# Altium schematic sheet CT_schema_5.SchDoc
size 298 x 247 mm
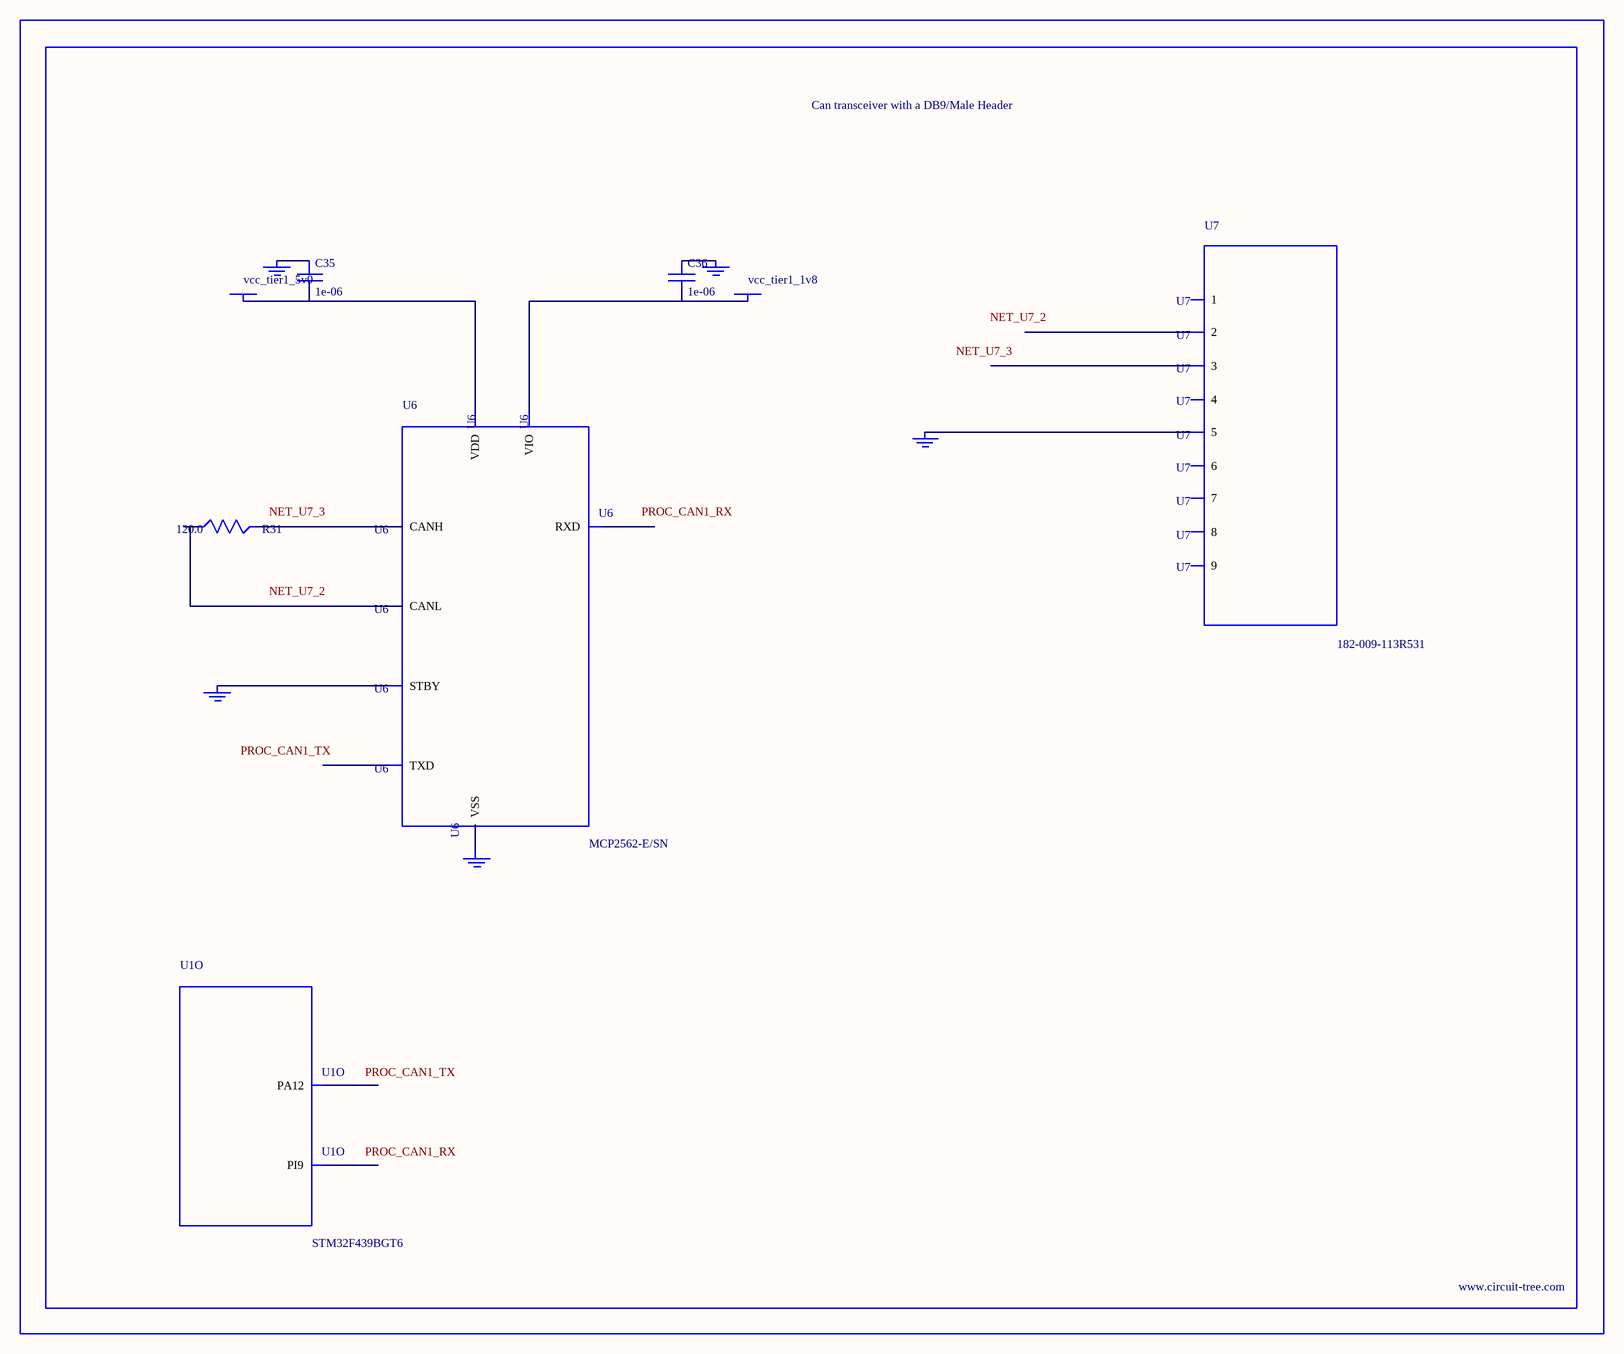
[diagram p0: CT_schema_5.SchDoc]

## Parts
BORDER4  (no value)
C35  1e-06  [C0603]
C36  1e-06  [C0603]
GND_INSTANCE_4_0  (no value)
GND_INSTANCE_4_1  (no value)
GND_INSTANCE_4_2  (no value)
GND_INSTANCE_4_3  (no value)
GND_INSTANCE_4_4  (no value)
POWER_INSTANCE_4_0  vcc_tier1_5v0
POWER_INSTANCE_4_1  vcc_tier1_1v8
R31  120.0  [R0603]
U1  STM32F439BGT6  [LQFP208]  (part O of 18)
U6  MCP2562-E/SN  [SOIC-8]
U7  182-009-113R531  [182-009-MALE]

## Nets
NetC35_1: C35.1 GND_INSTANCE_4_0.0(GND)
NetC35_2: C35.2 POWER_INSTANCE_4_0.0(PWR) U6.3(VDD)
NetC36_1: C36.1 GND_INSTANCE_4_1.0(GND)
NetC36_2: C36.2 POWER_INSTANCE_4_1.0(PWR) U6.5(VIO)
NetGND_INSTANCE_4_2_0: GND_INSTANCE_4_2.0(GND) U6.8(STBY)
NetGND_INSTANCE_4_3_0: GND_INSTANCE_4_3.0(GND) U6.2(VSS)
NetGND_INSTANCE_4_4_0: GND_INSTANCE_4_4.0(GND) U7.5
NetR31_1: R31.1 U6.6(CANL)
NetR31_2: R31.2 U6.7(CANH)

Not connected (* = marked no-connect by the designer): U1 11(PI9) 146(PA12); U6 1(TXD) 4(RXD); U7 1 2 3 4 6 7 8 9

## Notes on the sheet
- Labels drawn without touching a wire or pin: NET_U7_2, NET_U7_3, PROC_CAN1_RX, PROC_CAN1_TX

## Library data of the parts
BORDER4 = BORDER_PAGE4
C35 C36 = C0603C105K3RACTU
GND_INSTANCE_4_0-GND_INSTANCE_4_4 = GND
POWER_INSTANCE_4_0 POWER_INSTANCE_4_1 = PWR
R31 = RC0603JR-07120RL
